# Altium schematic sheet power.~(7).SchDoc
size Letter
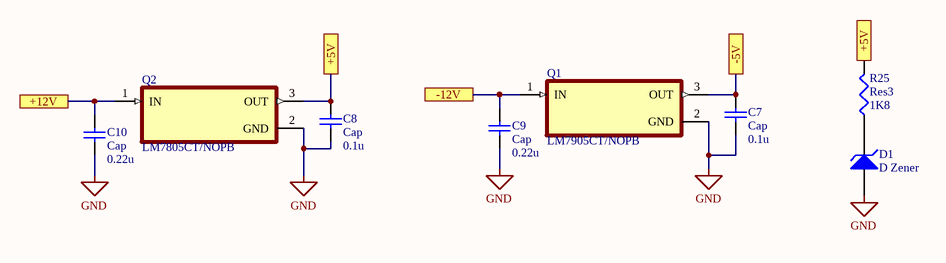
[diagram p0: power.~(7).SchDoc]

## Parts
C7  Cap  value 0.1u  [RAD-0.3]
C8  Cap  value 0.1u  [RAD-0.3]
C9  Cap  value 0.22u  [RAD-0.3]
C10  Cap  value 0.22u  [RAD-0.3]
D1  D Zener  [DIODE-0.7]
Q1  LM7905CT/NOPB  [TO254P1054X470X1955-3]
Q2  LM7805CT/NOPB  [TO254P1054X470X1955-3]
R25  Res3  value 1K8  [J1-0603]

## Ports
+5V, +12V, -5V, -12V

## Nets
GND: C7.1 C8.1 C9.1 C10.1 D1.1(A) Q1.2(GND) Q2.2(GND)
+5V: C8.2 Q2.3(OUT) R25.2 ; port +5V
+12V: C10.2 Q2.1(IN) ; port +12V
-5V: C7.2 Q1.3(OUT) ; port -5V
-12V: C9.2 Q1.1(IN) ; port -12V
NetD1_2: D1.2(K) R25.1

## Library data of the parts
C7-C10 = Cap: Capacitor
D1 = D Zener: Zener Diode
Q1 Q2 = LM7805CT/NOPB: 1.5-A, 30-V, linear voltage regulator 3-TO-220 0 to 125; MF: Texas Instruments
R25 = Res3: Resistor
